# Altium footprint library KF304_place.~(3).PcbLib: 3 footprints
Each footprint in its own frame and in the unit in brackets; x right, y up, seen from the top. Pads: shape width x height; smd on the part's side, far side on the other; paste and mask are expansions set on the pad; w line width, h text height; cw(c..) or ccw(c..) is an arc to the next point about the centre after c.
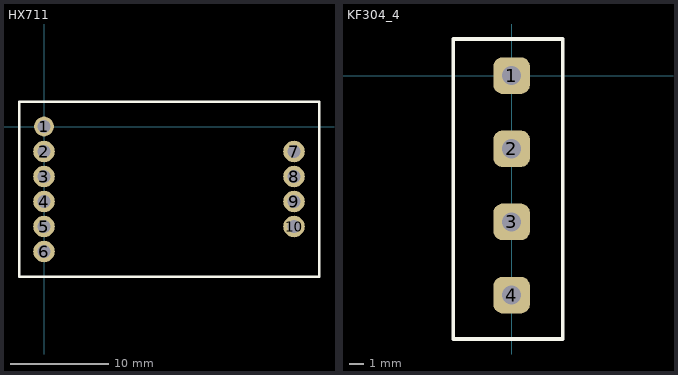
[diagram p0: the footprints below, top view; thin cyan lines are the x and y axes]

## HX711 [mm]
height 5
pads (10):
  round 2 hole 1.3 paste+0 mask+0.102: 1(0,0)
  round 2.2 hole 1.3 paste+0 mask+0.102: 2(0,-2.54) 3(0,-5.08) 4(0,-7.62) 5(0,-10.16) 6(0,-12.7) 7(25.4,-2.54) 8(25.4,-5.08) 9(25.4,-7.62) 10(25.4,-10.16)
Top Overlay:
  lines w0.254: -2.54,-15.24 27.94,-15.24 27.94,2.54 -2.54,2.54 -2.54,-15.24

## KF304_4 [mm]
height 14.5
pads (4):
  rrect50% 2.5x2.5 hole 1.3 paste+0 mask+0.102: 1(0,0) 2(0,-5) 3(0,-10) 4(0,-15)
Top Overlay:
  lines w0.254: -4,-18 -4,2.5 3.5,2.5 3.5,-18 -4,-18

## PCBComponent_1 [mm]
